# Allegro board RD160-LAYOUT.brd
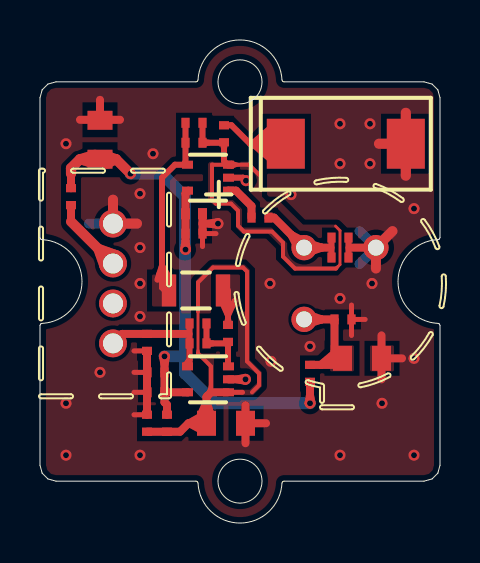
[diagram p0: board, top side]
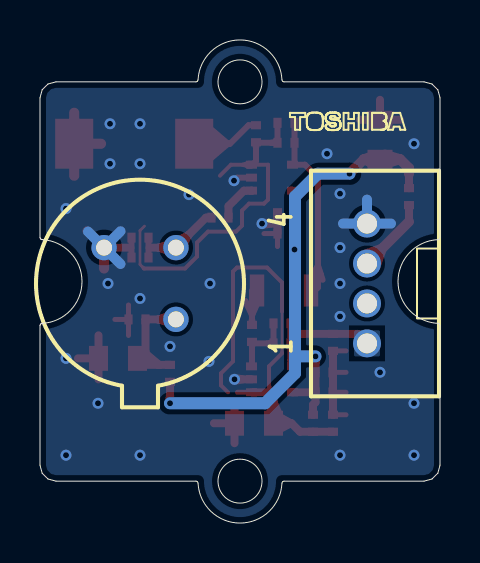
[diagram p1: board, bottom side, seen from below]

Outline 20 x 24.2 mm; copper layers: TOP, BOTTOM. Coordinates in mm from the lower left corner of the outline.
Outline path: circle c10,22.1 r1.1 ; circle c10,2.1 r1.1 ; 0,21.3 0.11,21.7 0.4,21.99 0.8,22.1 7.8,22.1 7.87,22.13 7.9,22.2 arc(10,24.2) 12.1,22.2 12.13,22.13 12.2,22.1 19.2,22.1 19.6,21.99 19.89,21.7 20,21.3 20,14.3 19.97,14.23 19.9,14.2 19.9,14.2 arc(17.9,12.1) 19.9,10 19.97,9.97 20,9.9 20,2.9 19.89,2.5 19.6,2.21 19.2,2.1 12.2,2.1 12.13,2.07 12.1,2 arc(10,0) 7.9,2 7.87,2.07 7.8,2.1 0.8,2.1 0.4,2.21 0.11,2.5 0,2.9 0,9.9 0.03,9.97 0.1,10 arc(2.1,12.1) 0.1,14.2 0.03,14.23 0,14.3 0,21.3

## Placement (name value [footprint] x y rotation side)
C1  -  [DC834K0ACP]  7.9 10 180 top
C2  -  [KC00060ATP]  16.1 8.25 180 top
C3  -  [DC834K0ACP]  15.15 10.2 180 top
C4  -  [KC00050ACP]  5.8 6.55 0 top
C5  -  [DC834K0ACP]  5.8 7.55 0 top
C6  -  [DC834K0ACP]  7.7 20.05 180 top
C7  -  [KC00060ATP]  9.3 5 0 top
C8  -  [KC00140ACP]  7.8 11.65 0 top
C9  -  [DC834K0ACP]  15 13.3 180 top
C10  -  [KC01320AKP]  7.7 15.5 180 top
C11  -  [DC834K0ACP]  7.7 14.5 180 top
C12  -  [KC00060ATP]  3 19.2 270 top
C13  -  [DC847R0ACP]  15.29 19 180 top
CN1  -  [CUP10060ATP]  3.65 9 90 bottom
NOREF  -  []  8.35 18.85 0 top
PIR1  -  [RDP10040ATP]  15 12 90 bottom
R1  -  [DR824K0ACP]  7.9 9 180 top
R2  -  [KC00050ACP]  5.35 9.05 270 top
R3  -  [KC00050ACP]  13.5 7.5 270 top
R4  -  [DR824K0ACP]  5.35 5 90 top
R5  -  [DR824K0ACP]  9.4 9.5 90 top
R6  -  [DR824K0ACP]  7.7 19.05 180 top
R7  -  [DR824K0ACP]  6.35 5 90 top
R8  -  [DR824K0ACP]  11 15.3 180 top
R9  -  [KC00050ACP]  1.55 16.35 270 top
R10  -  [DR824K0ACP]  15 14.3 0 top
R11  -  [DR824K0ACP]  9.2 19.5 90 top
U1  -  [MM00380ACP]  8.4 7.2 90 top
U2  -  [MM00380ACP]  8.4 17.3 90 top

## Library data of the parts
C1 C6 = GDM030000025: alternate symbols: (T:DC834K0ACP;B:DC834K0BCP)
C2 = K0301764: alternate symbols: (T:KC00060ATP;B:KC00060BTP)
C3 C5 C11 = G36030133036: alternate symbols: (T:DC834K0ACP;B:DC834K0BCP)
C4 = GDM030001142: alternate symbols: (T:KC00050ACP;B:KC00050BCP)
C7 C12 = GDM030002009: alternate symbols: (T:KC00060ATP;B:KC00060BTP)
C8 = GDM030002243: alternate symbols: (T:KC00140ACP;B:KC00140BCP)
C9 = G36030133142: alternate symbols: (T:DC834K0ACP;B:DC834K0BCP)
C10 = GAS030000012: alternate symbols: (T:KC01320AKP;B:KC01320BKP)
C13 = K0301781: alternate symbols: (T:DC847R0ACP;B:DC847R0BCP)
CN1 = K22S001P: alternate symbols: (T:CUP10060ATP;B:CUP10060BTP)
PIR1 = K47S002C: alternate symbols: (T:RDP10040ATP;B:RDP10040BTP)
R1 R6 = G510110J8105: alternate symbols: (T:DR824K0ACP;B:DR824K0BCP)
R2 R9 = GDM010000374: alternate symbols: (T:KC00050ACP;B:KC00050BCP)
R3 = GDM010004244: alternate symbols: (T:KC00050ACP;B:KC00050BCP)
R4 R7 R8 R11 = GDM010001350: alternate symbols: (T:DR824K0ACP;B:DR824K0BCP)
R5 = GDM010001348: alternate symbols: (T:DR824K0ACP;B:DR824K0BCP)
R10 = G510110J0109: alternate symbols: (T:DR824K0ACP;B:DR824K0BCP)
U1 U2 = K47S002A: alternate symbols: (T:MM00380ACP;B:MM00380BCP)

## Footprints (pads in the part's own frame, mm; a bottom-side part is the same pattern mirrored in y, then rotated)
CUP10060ATP
  round 1.397 hole 1: 1(0,0) 2(2,0) 3(4,0) 4(6,0)
DC834K0ACP
  rect 0.41x0.5 smd: 1(-0.425,0) 2(0.425,0)
DC847R0ACP
  rect 1.9x2.5 smd: 1(-3,0) 2(3,0)
DR824K0ACP
  rect 0.41x0.5 smd: 1(-0.425,0) 2(0.425,0)
KC00050ACP
  rect 0.41x0.5 smd: 1(-0.425,0) 2(0.425,0)
KC00060ATP
  rect 0.95x1.25 smd: 1(-0.975,0) 2(0.975,0)
KC00140ACP
  rect 0.72x1.6 smd: 1(-1.35,0) 2(1.35,0)
KC01320AKP
  rect 0.45x0.55 smd: 1(-0.425,0) 2(0.425,0)
MM00380ACP
  rect 0.4x0.55 smd: 1(-0.65,-1.025) 2(0,-1.025) 3(0.65,-1.025) 4(0.65,1.025) 5(-0.65,1.025)
RDP10040ATP
  round 1.27 hole 0.8: D(-1.796,-1.796) G(1.796,1.796) S(1.796,-1.796)

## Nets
GND: C2.1(TP-1) C3.1(TP-1) C4.1(TP-1) C5.1(TP-1) C7.2(TP-1) C9.1(TP-1) C10.1(TP-1) C11.1(TP-1) C12.1(TP-1) C13.1(TP-1) CN1.4 PIR1.G R2.2(TP-1) R4.2(TP-1) R10.2(TP-1) U1.2 U2.2
VCC: C4.2(TP-1) C5.2(TP-1) C10.2(TP-1) C11.2(TP-1) C12.2(TP-1) R3.2(TP-1) R7.2(TP-1) R9.1(TP-1) U1.5 U2.5
SIG45: C2.2(TP-1) C3.2(TP-1) PIR1.D R3.1(TP-1)
SIG48: C13.2(TP-1) R11.2(TP-1)
SIG49: C6.1(TP-1) R6.1(TP-1) R11.1(TP-1) U2.3
SIG50: C6.2(TP-1) C8.1(TP-1) R6.2(TP-1) U2.4
SIG52: C9.2(TP-1) PIR1.S R8.1(TP-1) R10.1(TP-1)
SIG53: C8.2(TP-1) R5.2(TP-1)
SIG54: C7.1(TP-1) R4.1(TP-1) R7.1(TP-1) U1.1
SIG57: C1.1(TP-1) R1.1(TP-1) R5.1(TP-1) U1.3
SIG62: C1.2(TP-1) CN1.1 R1.2(TP-1) R2.1(TP-1) U1.4
SIG63: CN1.3 R9.2(TP-1)
SIG64: R8.2(TP-1) U2.1

Pads without a net: CN1 2

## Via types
v1: diameter 0.55, hole 0.3, TOP to BOTTOM, 32 vias

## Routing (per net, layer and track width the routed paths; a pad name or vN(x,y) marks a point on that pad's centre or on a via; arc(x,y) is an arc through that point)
GND: length 40.6
  TOP w0.25: 8.12,13.85 C11.1 8.8,14.5 ; C3.1 16.26,10.2 ; C3.1 15.57,10.92 ; C3.1 15.57,9.4 ; R4.2 4.7,5.42 ; C4.1 4.7,6.55 ; R2.2 4.7,8.62 ; C5.1 4.7,7.55
  TOP w0.3: v1(10.3,17.15) 10.15,17.3 U2.2 9.39,17.3 ; R10.2 C9.1
  TOP w0.4: C2.1 17.07,7.2 ; C2.1 18.1,8.25 ; C2.1 17.07,9.4 ; C12.1 3,20.2 ; 3,20.2 3,21.2 ; 3,20.2 2,20.2 ; 3,20.2 4,20.2 ; R2.2 R4.2 ; 8.12,15 C11.1 ; 8.12,15 C10.1 ; 8.12,15 v1(8.9,15) ; v1(10.28,7.2) U1.2 ; C7.2 11.3,5 ; C7.2 10.28,5.9 ; C7.2 10.28,4 ; PIR1.G 15.47,13.8
  TOP w0.5: 4.85,15 CN1.4 3.65,16.2 ; 17.62,14.62 PIR1.G 16.8,12.75
  TOP w0.508: C13.1 18.29,20.55 ; C13.1 16.95,19 ; C13.1 18.29,17.4
  BOTTOM w0.5: PIR1.G 17.6,14.6 ; PIR1.G 15.97,12.97 ; PIR1.G 15.97,14.62 ; 2.45,15 CN1.4 ; CN1.4 3.65,16.2 ; CN1.4 4.85,15
  vias: v1(1.3,19) v1(1.3,6) v1(1.3,3.4) v1(3,7.55) v1(5,16.5) v1(5,13.8) v1(5,12) v1(5,10.35) v1(5,3.4) v1(5.65,18.5) v1(11.5,12) v1(11.55,8.1) v1(12.55,16.45) v1(13.5,8.85) v1(15,20) v1(15,18) v1(15,11.25) v1(15,3.4) v1(16.5,20) v1(16.5,18) v1(16.6,12) v1(17.1,6) v1(18.7,15.75) v1(18.7,8.25) v1(18.7,3.4)
VCC: length 34.3
  TOP w0.4: R9.1 1.55,17.5 ; v1(7.28,13.7) C11.2 C10.2 7.28,16.51 7.41,16.65 ; 6.22,6.6 C4.2 6.22,6.05 6.35,5.92 R7.2 ; 6.22,6.6 C5.2 v1(6.22,8.35) ; 6.22,6.6 6.28,6.55 U1.5 7.41,6.55 ; v1(13.5,6) R3.2
  TOP w0.5: 3.35,18 3.79,18.23 3.25,18.42 ; 3.8,18.22 v1(4.53,17.5) ; 2.73,18 2,18.22 2.75,18.45
  TOP w0.508: 1.55,17.5 1.55,17.77 2,18.22 ; C12.2 3.8,18.22
  BOTTOM w0.6: v1(4.53,17.5) 6.1,17.5 7.25,16.35 7.25,8.35 ; v1(13.5,6) 8.75,6 7.25,7.5 7.25,8.35 ; 7.25,8.35 v1(6.22,8.35)
SIG45: length 9.4
  TOP w0.4: 14.07,10.2 13.3,10.2 ; 14.07,10.2 13.3,9.95 PIR1.D 13.3,10.47 14.07,10.2 ; 14.07,10.2 C3.2 14.72,8.6 15.07,8.25 ; 14.05,7.92 14.85,8.17 ; 14.05,7.92 R3.1 ; 14.05,7.92 14.85,8.6 ; 14.05,7.92 14.8,7.92 15.12,8.25
SIG48: length 10.8
  TOP w0.3: 10.6,19 11.65,18.1 ; 10.6,19 11.65,18.4 ; 10.6,19 11.65,18.7 ; 10.6,19 11.65,19.9 ; 10.6,19 10.5,19 9.57,19.92 R11.2 ; 10.6,19 11.65,19.6 ; 10.6,19 C13.2 ; 10.6,19 11.65,19.3
SIG49: length 18.5
  TOP w0.14: 14.78,14.87 15,14.65 15,12.95 14.78,12.72
  TOP w0.2: 11,17.4 10.45,17.95 9.56,17.95 ; 9.39,17.95 8.6,17.95 8.6,16.2 8.8,16 9.55,16 9.9,15.65 9.9,14.9 10.2,14.6 11.6,14.6 12.15,14.05 12.15,13.35 12.75,12.75 14.8,12.75
  TOP w0.3: 9.39,17.95 9.2,18.14 R11.1 ; R6.1 8.12,19 ; R6.1 C6.1 ; R6.1 9.2,19.05
  TOP w0.4: U2.3 9.56,17.95
SIG50: length 11
  TOP w0.3: U2.4 6.75,17.95 6.1,17.3 6.1,12.9 ; U2.4 7.41,17.95 ; U2.4 7.28,18.05 R6.2 C6.2 ; 6.1,12.9 6.1,11.8 6.25,11.65 ; 6.1,12.9 5.95,12.44 5.87,12.19 ; 6.1,12.9 6.53,12.18
SIG52: length 9.1
  TOP w0.3: R10.1 C9.2
  TOP w0.4: 14.07,13.8 13.32,14.04 ; 14.07,13.8 13.3,13.52 PIR1.S ; 14.07,13.8 PIR1.S ; 14.07,13.8 14.53,13.8 ; 13.32,14.04 13.3,14.05 PIR1.S ; 13.32,14.04 PIR1.S ; 13.32,14.04 12.57,14.42 ; PIR1.S 12.57,14.42 ; PIR1.S 12.95,13.67 12.57,14.42 ; 12.57,14.42 11.7,15.3 11.43,15.3
SIG53: length 4.1
  TOP w0.3: 9.72,11.12 9.61,10.88 9.4,10.4 ; 9.4,10.4 9.4,11.65 ; 9.4,10.4 9.07,11.12 ; 9.4,10.4 9.22,11.12 ; 9.4,10.4 R5.2
SIG54: length 24.8
  TOP w0.14: 7.9,8.5 7.9,10.6
  TOP w0.2: 8.4,6.4 8.55,6.9 ; 8.55,6.9 8.55,6.55 ; 8.55,6.9 8.55,7.85 7.9,8.5 ; 10.6,6.55 10.95,6.9 10.95,7.5 10.35,8.1 10.35,12.6 10.15,12.8 8.65,12.8 7.9,12.05 7.9,10.6
  TOP w0.25: 9.39,6.55 U1.1 10.12,6.55
  TOP w0.4: 8.05,5.42 8.32,6.05 ; 8.32,6.05 8.32,6.32 8.55,6.55 9.39,6.55 ; 8.32,6.05 8.58,5.3 ; 8.32,6.05 8.32,5 7.47,5 ; 8.05,5.33 7.47,5 ; 7.47,5 7.42,5 7,4.57 R7.1 R4.1 ; 7.47,5 8.05,4.68
SIG57: length 3.3
  TOP w0.3: 8.32,10 8.32,9 9.38,9 ; R5.1 9.4,7.86
SIG62: length 7.4
  TOP w0.3: 7.47,8.16 R1.2 C1.2 ; 7.47,8.16 7.47,7.85 ; 7.47,8.16 7.25,7.9
  TOP w0.4: 4.12,9.47 3.55,9.3 CN1.1 4.12,9.47 ; 4.12,9.47 R2.1 7.42,9.47
SIG63: length 3.8
  TOP w0.4: R9.2 1.55,15.1
  TOP w0.5: 1.55,15.1 CN1.3
SIG64: length 2.1
  TOP w0.4: R8.2 10.57,15.87 9.8,16.65 U2.1 9.39,16.65

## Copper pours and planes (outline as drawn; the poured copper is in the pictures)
GND on TOP: 16.57,7.6 16.52,7.62 16.5,7.67 16.5,8.82 16.52,8.88 16.57,8.9 17.62,8.9 17.68,8.88 17.7,8.82 17.7,7.67 17.68,7.62 17.62,7.6
GND on TOP: 0.37,21.55 0.55,21.73 0.8,21.8 7.8,21.8 8.08,21.91 8.2,22.19 10,23.9 11.8,22.19 11.81,22.12 11.95,21.89 12.2,21.8 19.2,21.8 19.45,21.73 19.63,21.55 19.7,21.3 19.7,14.55 19.68,14.5 19.64,14.47 18.76,14.16 18.07,13.53 17.94,13.33 17.83,13.13 17.81,13.08 17.76,12.97 17.72,12.85 17.6,11.97 17.81,11.11 17.82,11.11 18.55,10.19 19.64,9.73 19.68,9.7 19.7,9.65 19.7,2.9 19.63,2.65 19.45,2.47 19.2,2.4 12.2,2.4 11.92,2.29 11.8,2.01 11.8,1.98 9.98,0.3 8.2,2.01 8.1,2.26 7.87,2.39 7.85,2.4 0.8,2.4 0.55,2.47 0.37,2.65 0.3,2.9 0.3,9.65 0.31,9.7 0.35,9.72 0.36,9.73 2.4,12.1 0.36,14.47 0.35,14.48 0.31,14.5 0.3,14.55 0.3,21.3 ; 10 cut-outs
GND on BOTTOM: 8.11,2.31 7.9,2.4 0.8,2.4 0.55,2.47 0.37,2.65 0.3,2.9 0.3,9.65 0.32,9.7 0.36,9.73 2.4,12.1 0.36,14.47 0.32,14.5 0.3,14.55 0.3,21.3 0.37,21.55 0.55,21.73 0.8,21.8 7.9,21.8 8.11,21.89 8.2,22.1 10,23.9 11.8,22.1 11.89,21.89 12.1,21.8 19.2,21.8 19.45,21.73 19.63,21.55 19.7,21.3 19.7,14.55 19.68,14.5 19.64,14.47 17.6,12.1 19.64,9.73 19.68,9.7 19.7,9.65 19.7,2.9 19.63,2.65 19.45,2.47 19.2,2.4 12.1,2.4 11.89,2.31 11.8,2.1 10,0.3 8.2,2.1 ; 10 cut-outs
SIG45 on TOP: 14.57,7.6 14.52,7.62 14.5,7.67 14.5,8.82 14.52,8.88 14.57,8.9 15.62,8.9 15.68,8.88 15.7,8.82 15.7,7.67 15.68,7.62 15.62,7.6
SIG49 on TOP: 13.95,14.27 13.92,14.28 13.9,14.3 13.84,14.35 13.57,14.56 13.22,14.64 13.01,14.64 12.98,14.65 12.96,14.66 11.92,15.7 11.91,15.72 11.9,15.75 11.9,15.8 11.07,15.8 11.02,15.82 11,15.87 11,16.02 11,16.07 10.53,16.55 10.51,16.6 10.53,16.65 10.71,16.83 10.83,17.05 10.85,17.17 10.79,17.42 10.71,17.52 10.67,17.55 10.45,17.68 10.32,17.7 10.07,17.7 10.02,17.72 10,17.77 10,18.02 10.02,18.08 10.07,18.1 10.42,18.1 10.45,18.09 10.47,18.08 11.08,17.47 11.09,17.45 11.1,17.42 11.1,16.35 11.35,16.1 11.97,16.1 12,16.09 12.02,16.08 13.15,14.95 14.77,14.95 14.8,14.94 14.82,14.93 14.84,14.85 14.77,14.8 14.1,14.8 14.1,14.35 14.08,14.3 14.03,14.27
SIG49 on TOP: 12.73,12.65 12.7,12.66 12.68,12.67 12.07,13.28 12.06,13.3 12.05,13.33 12.05,13.85 11.4,14.5 10.13,14.5 10.1,14.51 10.08,14.52 9.82,14.78 9.81,14.8 9.8,14.83 9.8,15.6 9.5,15.9 8.73,15.9 8.7,15.91 8.68,15.92 8.42,16.18 8.41,16.2 8.4,16.23 8.4,17.97 8.41,18 8.42,18.02 8.48,18.08 8.5,18.09 8.53,18.1 8.62,18.1 8.68,18.08 8.7,18.02 8.7,16.17 9.62,16.17 9.65,16.17 9.67,16.15 10.08,15.75 10.09,15.72 10.1,15.69 10.1,14.8 11.54,14.8 11.57,14.79 11.6,14.78 12.34,14.04 12.35,14.01 12.36,13.99 12.36,13.8 12.91,13 13.85,13.25 13.9,13.3 13.93,13.32 13.96,13.32 14.03,13.32 14.08,13.3 14.1,13.25 14.1,12.8 14.77,12.8 14.84,12.75 14.82,12.67 14.8,12.66 14.77,12.65
SIG50 on TOP: 5.6,12.37 5.62,12.43 5.67,12.45 6.72,12.45 6.78,12.43 6.8,12.37 6.8,10.92 6.78,10.87 6.72,10.85 5.67,10.85 5.62,10.87 5.6,10.92
SIG53 on TOP: 8.88,10.85 8.82,10.87 8.8,10.92 8.8,12.37 8.82,12.43 8.88,12.45 9.93,12.45 9.98,12.43 10,12.37 10,10.92 9.98,10.87 9.93,10.85
SIG54 on TOP: 10.07,6.4 10.02,6.42 10,6.47 10,6.6 10.02,6.65 10.07,6.67 10.5,6.67 10.85,7.02 10.85,7.42 10.67,7.6 10.45,7.73 10.32,7.75 10.07,7.75 10.02,7.77 10,7.82 10,8.32 9.88,8.32 9.82,8.35 9.8,8.4 9.8,8.52 9.82,8.58 9.88,8.6 9.9,8.6 9.9,10.52 9.92,10.58 9.97,10.6 10.25,10.6 10.25,12.7 8.68,12.7 8.55,12.57 8.55,10.57 8.53,10.52 8.47,10.5 7.88,10.5 7.82,10.52 7.8,10.57 7.8,12.12 7.81,12.15 7.82,12.17 8.58,12.93 8.6,12.94 8.63,12.95 10.19,12.95 10.22,12.94 10.25,12.93 10.48,12.7 10.49,12.67 10.5,12.64 10.5,8.15 11.08,7.57 11.09,7.55 11.1,7.52 11.1,6.88 11.09,6.85 11.08,6.83 10.67,6.42 10.65,6.41 10.62,6.4
SIG62 on BOTTOM: 3.08,8.35 3.02,8.37 3,8.42 3,9.57 3.02,9.63 3.08,9.65 4.22,9.65 4.28,9.63 4.3,9.57 4.3,8.42 4.28,8.37 4.22,8.35

Small or netless copper shapes (teardrops, artwork), in the pictures only: 16 on TOP

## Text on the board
Ref Des/Silkscreen Bottom: 4 | 1
SYMBOL-2-TOP: C5 | C4 | C6 | R6 | C10 | C11 | U2 | C1 | R1 | C8 | U1 | R8 | C7 | R10 | C9 | C2 | C3 | C13 | C12 | R2 | R9 | R4 | R7 | R11 | R5 | R3
User.5: 4 | 1
User.6: CN1 | Gnd | Vcc | Out | NC | PIR1 | GROVE-B | 1
